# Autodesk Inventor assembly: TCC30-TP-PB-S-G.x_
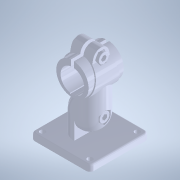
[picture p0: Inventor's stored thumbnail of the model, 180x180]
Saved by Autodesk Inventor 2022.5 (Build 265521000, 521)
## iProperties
Created: 2023-09
Part Number: TCC30-TP-PB-S-G.x_
Document SubType Name: Assembly
Designer: ImaoCorp
Sending System: SOLIDWORKS 2021-2021301
MC: AMD64
MC_MODEL: Intel64 Family 6 Model 60 Stepping 3, GenuineIntel
OS: Windows_NT
FRU: Parasolid Version 32.1, build 255,  1- 1-2021
FORMAT: text
GUISE: transmit
KEY: TCC30-TP-PB-S-G
FILE: TCC30-TP-PB-S-G.x_t
DATE: Fri Sep 15 15:37:36 2023
Author: ImaoCorp
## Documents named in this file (7)
- X:\14_SW2022-Inv2022\00_全2023-1023新製品(TCC)まで\t\tcc30-tp-pb-s-g\TCC30-TP-PB-S-G.iam
- X:\14_SW2022-Inv2022\00_全2023-1023新製品(TCC)まで\t\tcc30-tp-pb-s-g\TCC30-TP-PB-S-G_01.ipt
- X:\14_SW2022-Inv2022\00_全2023-1023新製品(TCC)まで\t\tcc30-tp-pb-s-g\TCC30-TP-PB-S-G_02.ipt
- X:\14_SW2022-Inv2022\00_全2023-1023新製品(TCC)まで\t\tcc30-tp-pb-s-g\TCC30-TP-PB-S-G_03.ipt
- X:\14_SW2022-Inv2022\00_全2023-1023新製品(TCC)まで\t\tcc30-tp-pb-s-g\TCC30-TP-PB-S-G_04.ipt
- X:\14_SW2022-Inv2022\00_全2023-1023新製品(TCC)まで\t\tcc30-tp-pb-s-g\TCC30-TP-PB-S-G_05.ipt
- X:\14_SW2022-Inv2022\00_全2023-1023新製品(TCC)まで\t\tcc30-tp-pb-s-g\TCC30-TP-PB-S-G_06.ipt
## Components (6 placed, 6 different names)
1. TCC30-TP-PB-S-G_01
2. TCC30-TP-PB-S-G_02
3. TCC30-TP-PB-S-G_03
4. TCC30-TP-PB-S-G_04
5. TCC30-TP-PB-S-G_05
6. TCC30-TP-PB-S-G_06
